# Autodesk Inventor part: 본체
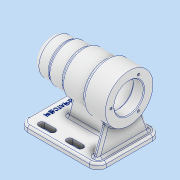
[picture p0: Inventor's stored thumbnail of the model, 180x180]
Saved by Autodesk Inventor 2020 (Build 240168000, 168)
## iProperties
Created: 2021-10
Part Number: 본체
Material: 알루미늄 6061
Document SubType Name: Modeling
Designer: user
Density: 2.7 g/cm^3
Appearance: 알루미늄 - 평지
Mass: 694.145 g
Surface Area: 699.007 cm^2
Volume: 257.091 cm^3
Author: user
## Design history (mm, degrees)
sketch "스케치1"
  geometry: L1 (-130, 0)-(0, 0); L2 (0, 21)-(-15, 21); L3 (-15, 21)-(-15, 24); L4 (-15, 24)-(-69, 24); L5 (-69, 24)-(-69, 21); L6 (-69, 21)-(-81, 21); L7 (-81, 21)-(-81, 17.5); L8 (-81, 17.5)-(-99, 17.5); L9 (-99, 17.5)-(-99, 16); L10 (-99, 16)-(-103, 16); L11 (-103, 16)-(-103, 10.5); L12 (-103, 10.5)-(-106, 10.5); L13 (-106, 10.5)-(-106, 0); L14 (0, 34)-(-32, 34); L15 (0, 34)-(0, 21); L16 (-32, 30)-(-66, 30); L17 (-32, 34)-(-32, 30); L18 (-66, 30)-(-66, 27); L19 (-66, 27)-(-88, 27); L20 (-88, 27)-(-88, 25); L21 (-88, 25)-(-112, 25); L22 (-112, 25)-(-112, 0); L23 (-112, 0)-(-106, 0); 2 further points
  constraints: 46 end point, 8 horizontal, 8 vertical, 6 perpendicular, 2 vertical alignment, 1 coincident, 1 point on line
  dimensions: "d0" = 130 distance of L1.start L1.end; "d1" = 15 distance of L2.start L2.end; "d2" = 3 distance of L2.end L3.end; "d3" = 54 distance of L3.end L4.end; "d4" = 3 distance of L4.end L5.end; "d5" = 12 distance of L5.end L6.end; "d6" = 3.5 distance of L6.end L7.end; "d7" = 18 distance of L7.end L8.end; "d8" = 1.5 distance of L8.end L9.end; "d9" = 4 distance of L9.end L10.end; "d10" = 5.5 distance of L10.end L11.end; "d11" = 3 distance of L11.end L12.end; "d12" = 10.5 distance of L12.end L13.end; "d13" = 21 distance of point (0, 0) L2.start; "d14" = 32 distance of L14.start L14.end; "d15" = 34 distance of point (0, 0) L14.start; "d16" = 34 distance of L16.start L16.end; "d17" = 4 distance of L14.end L16.start; "d18" = 3 distance of L16.end L18.end; "d19" = 22 distance of L18.end L19.end; "d20" = 2 distance of L19.end L20.end; "d21" = 24 distance of L20.end L21.end; "d93" = 46 horizontal distance of L16.end L21.end (derived); "d94" = 80 horizontal distance of L14.end L21.end (derived); "d95" = 30 distance between parallel lines of L1 L16 (derived)
revolve "회전1" sketch "스케치1" stored, may be unused: angle "d22" = 90 deg
node "작업 평면1"
sketch "스케치2"
  geometry: L1 (112, 45)-(0, 45); L2 (0, 45)-(0, -45); L3 (0, -45)-(112, -45); L4 (112, -45)-(112, 45); 2 further points
  constraints: 8 end point, 2 coincident, 2 parallel, 1 horizontal, 1 midpoint, 1 perpendicular
  dimensions: "d24" = 90 distance of L1.end L2.end; "d25" = 112 distance of L1.start L1.end
extrude "돌출1" join sketch "스케치2" distance "d26" = 8; taper "d27" = 0 deg
sketch "스케치3"
  geometry: L1 (-85, 4)-(-8, 4); L2 (-8, 4)-(-8, -4); L3 (-8, -4)-(-85, -4); L4 (-85, -4)-(-85, 4); L5 (0, -45)-(0, 45) reference; L6 (0, 45)-(-112, 45) reference; 3 further points
  constraints: 8 end point, 2 midpoint, 2 parallel, 1 horizontal, 1 horizontal alignment, 1 perpendicular
  dimensions: "d28" = 8 distance between parallel lines of L5 L2; "d31" = 77 distance of L1.start L1.end; "d32" = 8 distance between parallel lines of L3 L1
extrude "돌출2" join sketch "스케치3" stored distance "d33" = 8; taper "d34" = 0 deg
feature "면 기울기1" dims angle "d35" = 15 deg
node "작업 평면2"
sketch "스케치5"
  geometry: L1 (45, -62)-(-45, -62) reference; L2 (-37, -62)-(-23.409, -24.658); 2 further points
  constraints: 2 end point, 1 point on line, 2 other
  dimensions: "d37" = 110 deg angle of L2 L1; "d38" = 8 distance of L1.end L2.start
feature "리브1" sketch "스케치5" dims "d39" = 1, "d40" = 8, "d41" = 0, "d42" = 0, "d43" = 1, "d44" = 1
sketch "스케치6"
  geometry: L1 (23.409, -24.658)-(37, -62); L2 (-45, -62)-(45, -62) reference; A1 r 34 centre (0, 0) between (4, -33.764) and (-4, -33.764) reference; 1 further point
  constraints: 2 end point, 1 point on circle, 1 point on line
  dimensions: "d45" = 110 deg angle of L2 L1; "d46" = 8 distance of L2.end L1.end
feature "리브2" sketch "스케치6" dims "d47" = 1, "d48" = 8, "d49" = 0, "d50" = 0, "d51" = 1, "d52" = 1
sketch "스케치7"
  geometry: L1 (-92, 33)-(-77, 33); L2 (-92, 28.5)-(-77, 28.5); L3 (-77, 37.5)-(-92, 37.5); L4 (-112, -45)-(-112, 45) reference; L5 (-52, 33)-(-37, 33); L6 (-52, 28.5)-(-37, 28.5); L7 (-37, 37.5)-(-52, 37.5); L8 (-92, -37.5)-(-77, -37.5); L9 (-92, -33)-(-77, -33); L10 (-77, -28.5)-(-92, -28.5); L11 (-52, -37.5)-(-37, -37.5); L12 (-52, -33)-(-37, -33); L13 (-37, -28.5)-(-52, -28.5); A1 r 4.5 centre (-92, 33) between (-92, 37.5) and (-92, 28.5); A2 r 4.5 centre (-77, 33) between (-77, 28.5) and (-77, 37.5); A3 r 4.5 centre (-52, 33) between (-52, 37.5) and (-52, 28.5); A4 r 4.5 centre (-37, 33) between (-37, 28.5) and (-37, 37.5); A5 r 4.5 centre (-92, -33) between (-92, -28.5) and (-92, -37.5); A6 r 4.5 centre (-77, -33) between (-77, -37.5) and (-77, -28.5); A7 r 4.5 centre (-52, -33) between (-52, -28.5) and (-52, -37.5); A8 r 4.5 centre (-37, -33) between (-37, -37.5) and (-37, -28.5); 5 further points
  constraints: 32 end point, 16 point on circle, 16 tangent, 8 centre point, 4 horizontal, 4 midpoint, 4 parallel, 2 horizontal alignment, 2 vertical alignment
  dimensions: "d54" = 9 distance between parallel lines of L2 L3; "d55" = 15 distance of L1.start L1.end; "d56" = 20 distance from line of L4 L1.start; "d57" = 33 vertical distance of point (0, 0) point (-84.5, 33); "d58" = 9 diameter of A4; "d59" = 15 distance of L5.start L5.end; "d60" = 9 diameter of A6; "d61" = 15 distance of L9.start L9.end; "d62" = 9 diameter of A8; "d63" = 15 distance of L12.start L12.end; "d64" = 33 vertical distance of point (-84.5, -33) point (0, 0); "d65" = 25 distance of L1.end L5.start
extrude "돌출3" cut sketch "스케치7" distance "d66" = 8; taper "d67" = 0 deg
sketch "스케치8" dims "d68" = 52
  geometry: C1 r 10.5 at (0, 0) reference; 5 further points
  constraints: 2 horizontal alignment, 1 coincident, 6 other
  dimensions: "d71" = 360 deg dimension on point (0, 0) point (-26, 0) (derived)
hole "구멍1" sketch "스케치8" at (-26, 0), (13, -22.517), (13, 22.517) diameter "d73" = 3.242; stored, may be unused: countersink angle "d77" = 90 deg, drill point angle "d79" = 118 deg; dims "d74" = 8, "d75" = 8, "d76" = 10, "d78" = 11
fillet "모깎기1" dims "d80" = 0.3
fillet "모깎기2" dims "d81" = 3
chamfer "모따기1" distance "d82" = 1; stored, may be unused: second distance "d83" = 2, angle "d84" = 45 deg
fillet "모깎기3" dims "d85" = 12
fillet "모깎기4" dims "d86" = 3
fillet "모깎기5" dims "d87" = 8
fillet "모깎기6" dims "d88" = 3
sketch "스케치10"
  geometry: L1 (-109, -33)-(-109, 33) reference; L2 (-112, 33)-(-112, -33) reference; 3 further points
  constraints: 1 horizontal alignment, 1 midpoint, 1 other
  dimensions: "d89" = 12 distance from line of point (-100, 0) L2
feature "엠보싱1" sketch "스케치10" dims "d0" = 130, "d1" = 15, "d2" = 3, "d3" = 54, "d4" = 3, "d5" = 12, "d6" = 3.5, "d7" = 18, "d8" = 1.5, "d9" = 4, "d10" = 5.5, "d11" = 3, "d12" = 10.5, "d13" = 21, "d14" = 32, "d15" = 34, "d16" = 34, "d17" = 4, "d18" = 3, "d19" = 22, "d20" = 2, "d21" = 24, "d90" = 0.5, "d91" = 0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
fillet "모깎기7" dims "d92" = 3
node "솔리드1"
feature "A9D066F2-1C7D-4E18-AEED-F7BC21143FA4" dims "d73" = 3.242, "d74" = 8, "d75" = 8, "d76" = 10, "d77" = 90 deg, "d78" = 11, "d79" = 118 deg
other parameters: "d36" = -12
